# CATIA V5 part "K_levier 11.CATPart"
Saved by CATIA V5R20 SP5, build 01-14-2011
Part number: levier 11
Bounding box of the stored display mesh (mm): x -108.616 to 108.616, y -47.968 to 534.05, z -24.993 to 381
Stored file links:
  G:\Khaled_CFAO_2011\SIL\SIL_GR1\gperrin\Khaled\CAD_CATIA\Khaled\K_levier 11.CATPart
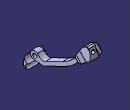
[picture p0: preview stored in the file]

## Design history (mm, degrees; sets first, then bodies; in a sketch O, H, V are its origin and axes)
Set1
  Plane1: type Angle, RefPlane face of Pocket2 from Sketch5.L5, Direction edge [face of Mirror1 | face of Pocket2 from Sketch5.L5], Angle -79
  Point1: type OnPlane, Support face of Mirror2, H -350.451, V -57.77, Direction (0.7975, -0.6033, 0)
  Point2: type OnPlane, Support face of Mirror3, H 350.451, V -57.77, Direction (0.7975, 0.6033, 0)
Body1 (main body)
  Sketch1 on yz-plane, origin (0, 0, 0), H (0, 1, 0), V (0, 0, 1)
    point P1 (0, 42)
    circle A1 centre (0, 64) radius 19
    point P2 (0, 64)
    arc A2 centre (0, 64) radius 39 from (25.9746, 93.0916) to (-37.108, 76) ccw
    point P3 (25.9746, 93.0916)
    spline S1 through (25.9746, 93.0916) (56, 67) (76, 60) (105, 71)
    spline S2 through (0, 25) (25.9746, 25) (64, 21) (123.6236, 42)
    line L1 (511.3811, 375.4801) -> (534.0496, 287)
    spline S3 through (443, 294) (453, 311) (457, 330) (457, 355) (465.635, 370)
    line L2 (465.635, 370) -> (493, 381)
    point P6 (465.635, 370)
    line L3 (511.3811, 375.4801) -> (493, 381)
    point P8 (493, 381)
    spline S4 through (465.635, 270.2769) (534.0496, 287)
    point P9 (534.0496, 287)
    arc A3 centre (0.4161, -0.6389) radius 25.6423 from (0, 25) to (-21.2775, -14.3107) ccw
    point P13 (-45, 29)
    arc A4 centre (-11.3822, 19.2614) radius 35 from (-45, 29) to (-21.2775, -14.3107) ccw
    line L4 (-37.108, 76) -> (-45, 29)
    point P15 (-45, 29)
    line L5 (105, 71) -> (262.9657, 146.5729)
    point P16 (105, 71)
    line L6 (351.4811, 207.3934) -> (443, 294)
    point P17 (443, 294)
    line L7 (123.6236, 42) -> (241.2541, 95.2912)
    point P18 (123.6236, 42)
    line L8 (397.1128, 202.5153) -> (465.635, 270.2769)
    point P19 (465.635, 270.2769)
    arc A5 centre (113.616, 458.7503) radius 346.0637 from (262.9657, 146.5729) to (351.4811, 207.3934) ccw
    arc A6 centre (19.8392, 584.0236) radius 536.5482 from (241.2541, 95.2912) to (397.1128, 202.5153) ccw
    point P26 (25.9746, 93.0916)
    point P27 (105, 71)
    point P29 (123.6236, 42)
    point P30 (443, 294)
    point P31 (465.635, 270.2769)
    point P32 (534.0496, 287)
    radius A1 = 19
    distance P2 O = 64
    radius A2 = 39
    radius A5 = 346.0637
    radius A6 = 536.5482
    coincidence: P1 V, P2 V, P26 P3, P6 S3, P8 L2, P32 L1, P32 P9, P15 A4, L4 P13, P27 P16, L6 P30, P17 S3, P29 P18, P31 P19
    tangency: L5 A2, L7 A4, A5 L5, A5 L6, A6 L7, A6 L8
  Pad1: profile Sketch1, direction (1, 0, 0), length 30, mirrored extent
  Sketch2 on yz-plane, origin (0, 0, 0), H (0, 1, 0), V (0, 0, 1)
    arc A1 centre (0, 0) radius 25 from (0, 25) to (-5.9478, -24.2822) ccw
    arc A2 centre (-13, 10) radius 35 from (-47.0735, 18) to (-5.9478, -24.2822) ccw
    arc A3 centre (0, 64) radius 39 from (-38.4849, 70.3177) to (0, 25) ccw
    point P2 (0, 64)
    line L1 (-47.0735, 18) -> (-38.4849, 70.3177)
    coincidence: P2 V
    tangency: L1 A3
  Pad2: profile Sketch2, direction (1, 0, 0), length 90, mirrored extent
  Sketch3 on face of Pad1 from Sketch1.L1, origin (0, 570.1549, 146.0727), H (-1, 0, 0), V (0, -0.2482, 0.9687)
    circle A1 centre (0, 199) radius 16
    point P1 (0, 199)
    radius A1 = 16
    distance A1 O = 183
    coincidence: P1 V
  Pocket1: profile Sketch3, direction (0, -0.9687, -0.2482), through (limit type 3)
  Sketch4 on end face of Pad1, origin (30, 0, 0), H (0, 1, 0), V (0, 0, 1)
    spline S1 through (445.6818, 295.9958) (453, 311) (457, 330) (457, 355) (465.635, 370)
    point P1 (493, 381)
    point P2 (465.635, 370)
    line L1 (465.635, 370) -> (493, 381)
    point P3 (493, 381)
    line L2 (511.3811, 375.4801) -> (493, 381)
    point P5 (534.0496, 287)
    line L3 (511.3811, 375.4801) -> (534.0496, 287)
    spline S2 through (472.3466, 276.9141) (534.0496, 287)
    line L4 (472.3466, 276.9141) -> (445.2385, 250.1068)
    point P6 (472.3466, 276.9141)
    point P7 (445.2385, 250.1068)
    line L5 (445.2385, 250.1068) -> (422.3589, 273.2432)
    point P8 (445.2385, 250.1068)
    line L6 (445.6818, 295.9958) -> (422.3589, 273.2432)
    point P10 (445.6818, 295.9958)
    reference projected line E1 (397.1128, 202.5153) -> (465.635, 270.2769) from edge [face of Pad1 from Sketch1.L8 | end face of Pad1]
    point P11 (472.3466, 276.9141)
    point P12 (445.6818, 295.9958)
    point P13 (465.635, 370)
    point P14 (534.0496, 287)
    coincidence: P11 P6, P12 P10, P13 P2, P1 P3, P5 P14, P7 P8, L4 E1
    perpendicularity: L5 L4
  Pad3: profile Sketch4, direction (1, 0, 0), length 80
  Sketch5 on face of Pad3 from Sketch4.L6, origin (0, 69.373, -71.1117), H (1, 0, 0), V (0, 0.7158, 0.6983)
    line L1 (30, 672) -> (200, 672)
    line L2 (200, 672) -> (200, 446)
    line L3 (200, 446) -> (30, 446)
    line L4 (30, 616.208) -> (30, 672)
    point P4 (30, 446)
    reference projected line E1 (30, 522.4017) -> (30, 396.4146) from edge [face of Pad1 from Sketch1.L6 | end face of Pad1]
    line L5 (66.0484, 525.715) -> (110, 538.9444)
    point P5 (66.0484, 525.715)
    point P6 (110, 538.9444)
    reference projected line E2 (110, 591.6749) -> (110, 525.715) from edge [face of Pad3 from Sketch4.S1 | end face of Pad3]
    reference projected line E3 (30, 525.715) -> (110, 525.715) from edge [face of Pad3 from Sketch4.L6 | face of Pad3 from Sketch4.S1]
    arc A1 centre (53.3966, 506.0342) radius 23.3966 from (66.0484, 525.715) to (30, 506.0342) ccw
    point P8 (30, 506.0342)
    line L6 (110, 538.9444) -> (106.6563, 550.0532)
    line L7 (97.6443, 559.2371) -> (63.5161, 570.217)
    point P9 (104.5618, 557.0115)
    point P10 (30, 581)
    line L8 (97.6443, 559.2371) -> (106.6563, 550.0532)
    arc A2 centre (78.3126, 616.208) radius 48.3126 from (63.5161, 570.217) to (30, 616.208) cw
    line L9 (30, 446) -> (30, 506.0342)
    angle L7 L8 = 27.707
    length L8 = 12.867
    radius A2 = 48.3126
    horizontal: L1 H, L3 H
    vertical: L2 V, L4 V
    coincidence: L4 E1, P6 E2, P5 E3, P8 L4, P9 L6, P10 L4, L7 P9, L7 P10, L4 P4
    tangency: A1 L4, A2 L7, A2 L4, L9 A1
    perpendicularity: L6 L5
  Pocket2: profile Sketch5, direction (0, 0.6983, -0.7158), through (limit type 6), opposite side through (limit type 6)
  Mirror1: of Pad3, Sketch4, Pocket2, Sketch5, about yz-plane
  Sketch6 on Plane1, origin (-11.8045, 181.3613, -127.6235), H (-0.9979, -0.065, 0), V (-0.0373, 0.5735, 0.8184)
    line L1 (-89, 494) -> (-93.8, 478)
    line L2 (-93.8, 478) -> (-154, 493)
    line L3 (-154, 493) -> (-147.1, 516)
    line L4 (-147.1, 516) -> (-89, 494)
    parallelism: L3 L1
  Pocket3: profile Sketch6, direction (0.0532, -0.8167, 0.5747), through (limit type 6), opposite side through (limit type 6)
  Mirror2: of Pocket3, Sketch6, about yz-plane
  Mirror3: of the body so far, about yz-plane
